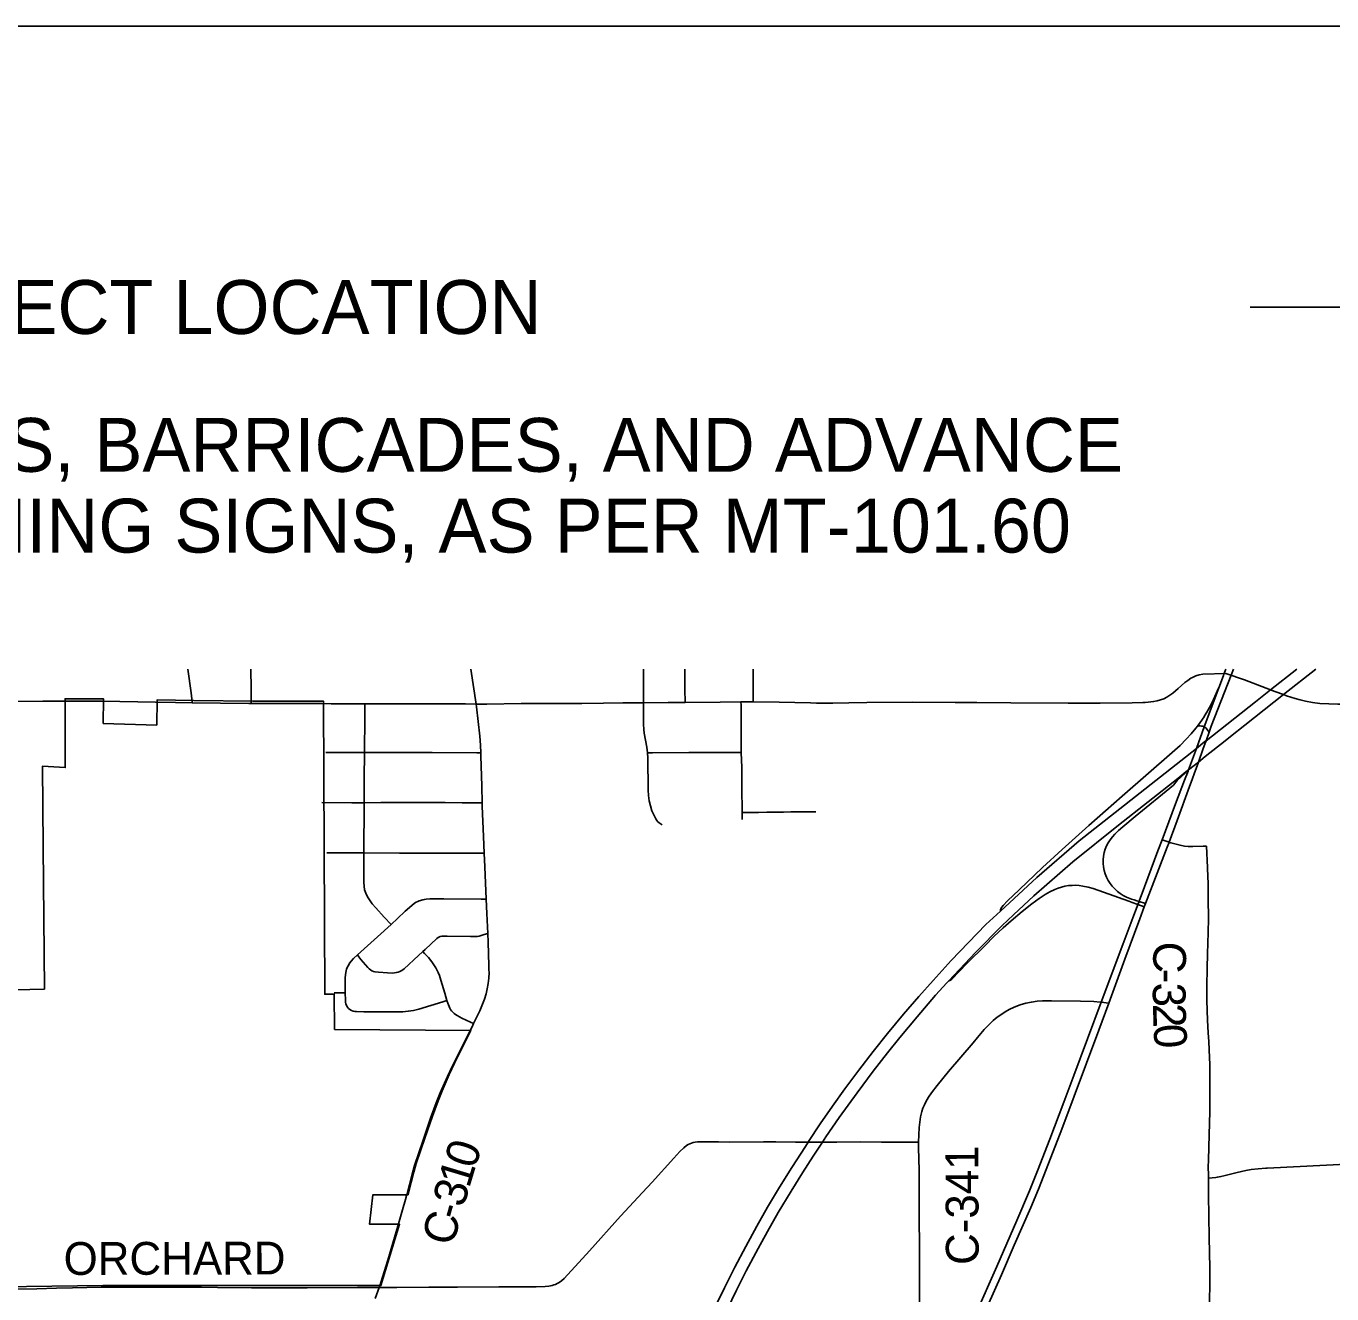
# Model space of a CAD drawing. Extents: x 40529 to 41139, y 15164 to 15584.
# Drawn here: x 40644 to 40711.9, y 15518.4 to 15584.3 of the extents above; entities that cross this region are included whole.
import ezdxf

# ---------------------------------------------------------------- set-up
doc = ezdxf.new("R2010")
doc.units = 0
for name, color, linetype in [('GM_X_Corporation', 7, 'Continuous'), ('GM_X_County_Road', 7, 'Continuous'), ('GM_X_County_Road_Text', 7, 'Continuous'), ('GM_X_Interchange_Ramps', 7, 'Continuous'), ('GM_X_Interstate_Route', 7, 'Continuous'), ('GM_X_State_Route', 7, 'Continuous'), ('GM_X_Township_Road', 7, 'Continuous'), ('SC_Scratch1', 7, 'Continuous'), ('SH_Data', 7, 'Continuous'), ('SH_Text', 7, 'Continuous')]:
    doc.layers.add(name, color=color, linetype=linetype)

msp = doc.modelspace()

# ---------------------------------------------------------------- linework, layer by layer
at = {"layer": 'GM_X_Corporation'}
msp.add_lwpolyline([(40633.428, 15533.98), (40645, 15534.243), (40644.942, 15541.646), (40644.909, 15545.837), (40646.082, 15545.763), (40646.076, 15549.343), (40648.075, 15549.336), (40648.062, 15548.055), (40650.838, 15547.972), (40650.859, 15549.285), (40652.768, 15549.256), (40655.835, 15549.22), (40659.511, 15549.213), (40659.574, 15533.977), (40660.069, 15533.984), (40660.082, 15532.153), (40667.169, 15532.086), (40666.326, 15530.389), (40666.05, 15529.799), (40665.675, 15528.948), (40665.465, 15528.43), (40665.172, 15527.644), (40664.775, 15526.501), (40664.33, 15525.179), (40664.204, 15524.732), (40663.932, 15523.646), (40663.906, 15523.553), (40662.067, 15523.549), (40661.908, 15522.019), (40663.467, 15522.024), (40662.492, 15518.827), (40648.03, 15518.837), (40632.149, 15518.628)], dxfattribs=at)
at = {"layer": 'GM_X_County_Road'}
for p, q in [((40667.442, 15549.06), (40667.161, 15550.883)), ((40647.999, 15549.211), (40650.78, 15549.16)), ((40659.423, 15549.088), (40659.915, 15549.082)), ((40675.065, 15549.123), (40676.138, 15549.135)), ((40703.102, 15542.012), (40703.464, 15541.887)), ((40705.414, 15541.679), (40705.47, 15540.568)), ((40705.48, 15540.149), (40705.492, 15539.688))]:
    msp.add_line(p, q, dxfattribs=at)
for points in [[(40702.228, 15549.146), (40702.385, 15549.156), (40702.659, 15549.19), (40702.84, 15549.228), (40703.016, 15549.279), (40703.187, 15549.345), (40703.35, 15549.428), (40703.505, 15549.525), (40703.653, 15549.634), (40703.936, 15549.874), (40704.29, 15550.181), (40704.439, 15550.297), (40704.595, 15550.404), (40704.676, 15550.452), (40704.849, 15550.531), (40705.031, 15550.585), (40705.219, 15550.613), (40706.419, 15550.658)], [(40706.419, 15550.658), (40707.391, 15550.324), (40708.745, 15549.806), (40708.957, 15549.724), (40709.415, 15549.557), (40709.572, 15549.5), (40710.017, 15549.355), (40710.288, 15549.281), (40710.562, 15549.218), (40710.93, 15549.15), (40711.301, 15549.103), (40711.767, 15549.07), (40712.233, 15549.056), (40712.768, 15549.055)], [(40629.727, 15549.202), (40632.453, 15549.203), (40633.472, 15549.215), (40634.586, 15549.231), (40635.982, 15549.24), (40637.122, 15549.236), (40638.834, 15549.216), (40640.349, 15549.212), (40642.683, 15549.194), (40644.917, 15549.219), (40646.002, 15549.217)], [(40646.002, 15549.217), (40647.802, 15549.214), (40647.999, 15549.211)], [(40650.78, 15549.16), (40651.808, 15549.141), (40652.687, 15549.13)], [(40652.687, 15549.13), (40655.628, 15549.095), (40655.75, 15549.095)], [(40655.75, 15549.095), (40657.396, 15549.09), (40658.508, 15549.099), (40659.423, 15549.088)], [(40659.915, 15549.082), (40659.991, 15549.081), (40661.654, 15549.081)], [(40661.654, 15549.081), (40666.89, 15549.07), (40667.442, 15549.06)], [(40667.442, 15549.06), (40668.008, 15549.057), (40669.778, 15549.087), (40672.947, 15549.102), (40674.065, 15549.112), (40675.065, 15549.123)], [(40667.687, 15546.537), (40667.67, 15546.931), (40667.632, 15547.395), (40667.458, 15548.915), (40667.442, 15549.06)], [(40676.138, 15549.135), (40677.422, 15549.149), (40678.304, 15549.154)], [(40678.304, 15549.154), (40680.125, 15549.165), (40681.212, 15549.173)], [(40681.212, 15549.173), (40681.617, 15549.176), (40681.84, 15549.175)], [(40681.84, 15549.175), (40683.199, 15549.169), (40684.819, 15549.126)], [(40684.819, 15549.126), (40685.142, 15549.117), (40685.978, 15549.107), (40686.816, 15549.122), (40687.749, 15549.14), (40690.122, 15549.157)], [(40690.122, 15549.157), (40692.349, 15549.149), (40693.469, 15549.142), (40695.24, 15549.129), (40698.222, 15549.118), (40699.887, 15549.109), (40701.553, 15549.124), (40702.108, 15549.139), (40702.228, 15549.146)], [(40667.753, 15543.936), (40667.733, 15544.788), (40667.694, 15546.371), (40667.687, 15546.537)], [(40667.866, 15541.321), (40667.825, 15542.182), (40667.757, 15543.765), (40667.753, 15543.936)], [(40703.464, 15541.887), (40703.566, 15541.852), (40704.042, 15541.724), (40704.276, 15541.678), (40704.459, 15541.659), (40704.698, 15541.659), (40705.237, 15541.673), (40705.414, 15541.679)], [(40667.97, 15538.924), (40667.9, 15540.599), (40667.866, 15541.321)], [(40705.47, 15540.568), (40705.472, 15540.489), (40705.48, 15540.149)], [(40705.492, 15539.688), (40705.501, 15538.944), (40705.508, 15537.922), (40705.49, 15537.19), (40705.471, 15536.071), (40705.454, 15535.327)], [(40668.044, 15537.134), (40668.001, 15538.177), (40667.97, 15538.924)], [(40668.112, 15535.245), (40668.111, 15535.475), (40668.063, 15536.687), (40668.044, 15537.134)], [(40667.31, 15532.457), (40667.631, 15533.122), (40667.779, 15533.464), (40667.876, 15533.726), (40667.959, 15533.993), (40668.025, 15534.265), (40668.073, 15534.541), (40668.101, 15534.821), (40668.113, 15535.101), (40668.112, 15535.245)], [(40705.454, 15535.327), (40705.432, 15534.394), (40705.432, 15533.649), (40705.463, 15532.624), (40705.498, 15531.976), (40705.534, 15531.514), (40705.573, 15530.676), (40705.579, 15530.349), (40705.587, 15529.93), (40705.581, 15527.879), (40705.555, 15526.667), (40705.516, 15525.362), (40705.503, 15524.989), (40705.513, 15524.586), (40705.522, 15524.408)], [(40693.277, 15531.449), (40693.511, 15531.725), (40693.861, 15532.14), (40694.123, 15532.421), (40694.325, 15532.608), (40694.537, 15532.786), (40694.769, 15532.944), (40695.001, 15533.102), (40695.228, 15533.225), (40695.499, 15533.343), (40695.731, 15533.427), (40696.017, 15533.506), (40696.313, 15533.57), (40696.604, 15533.615), (40696.886, 15533.639), (40697.349, 15533.644), (40698.869, 15533.615), (40699.554, 15533.595), (40699.885, 15533.571), (40699.937, 15533.564)], [(40699.937, 15533.564), (40699.958, 15533.561), (40700.314, 15533.521), (40700.334, 15533.519)], [(40667.073, 15531.978), (40667.267, 15532.368), (40667.31, 15532.457)], [(40663.806, 15523.425), (40663.814, 15523.454), (40663.84, 15523.547), (40664.111, 15524.632), (40664.238, 15525.078), (40664.682, 15526.399), (40665.078, 15527.541), (40665.371, 15528.326), (40665.581, 15528.844), (40665.955, 15529.694), (40666.231, 15530.283), (40667.073, 15531.978)], [(40690.447, 15526.289), (40690.45, 15526.672), (40690.472, 15527.045), (40690.503, 15527.324), (40690.546, 15527.611), (40690.615, 15527.882), (40690.67, 15528.055), (40690.749, 15528.233), (40690.818, 15528.385), (40690.956, 15528.622), (40691.123, 15528.859), (40691.415, 15529.229), (40692.006, 15529.954), (40693.277, 15531.449)], [(40662.402, 15518.733), (40663.317, 15518.731), (40664.993, 15518.747), (40665.737, 15518.752), (40666.482, 15518.756), (40668.616, 15518.769), (40670.106, 15518.768), (40670.57, 15518.765), (40671.035, 15518.781), (40671.217, 15518.799), (40671.396, 15518.836), (40671.484, 15518.862), (40671.569, 15518.894), (40671.652, 15518.931), (40671.732, 15518.974), (40671.808, 15519.024), (40671.88, 15519.078), (40672.013, 15519.203), (40673.331, 15520.645), (40674.949, 15522.44), (40676.085, 15523.67), (40676.591, 15524.216), (40677.717, 15525.455), (40678.038, 15525.795), (40678.244, 15525.987), (40678.371, 15526.106), (40678.465, 15526.165), (40678.549, 15526.205), (40678.642, 15526.244), (40678.731, 15526.274), (40678.825, 15526.289), (40678.943, 15526.303), (40679.113, 15526.307), (40680.047, 15526.3), (40680.606, 15526.292), (40682.374, 15526.302), (40683.027, 15526.298), (40684.052, 15526.291), (40684.706, 15526.292), (40685.445, 15526.292), (40685.895, 15526.293)], [(40685.895, 15526.293), (40686.195, 15526.293), (40687.406, 15526.299), (40688.524, 15526.295), (40689.8, 15526.289), (40690.384, 15526.289), (40690.447, 15526.289)], [(40690.486, 15517.482), (40690.499, 15519.736), (40690.48, 15523.462), (40690.467, 15524.818), (40690.446, 15526.018), (40690.447, 15526.289)], [(40705.522, 15524.408), (40705.892, 15524.453), (40705.98, 15524.468), (40706.069, 15524.483), (40706.158, 15524.502), (40706.316, 15524.542), (40707.001, 15524.71), (40707.458, 15524.813), (40707.735, 15524.86), (40708.106, 15524.907), (40708.504, 15524.939), (40708.571, 15524.944), (40711.644, 15525.091), (40712.669, 15525.151), (40712.857, 15525.156), (40713.047, 15525.147), (40713.141, 15525.136), (40713.326, 15525.095), (40713.416, 15525.064), (40713.494, 15525.031)], [(40663.375, 15521.926), (40663.589, 15522.649), (40663.806, 15523.425)], [(40662.402, 15518.733), (40662.448, 15518.862), (40662.493, 15518.989), (40662.847, 15520.147), (40663.375, 15521.926)], [(40632.089, 15518.534), (40635.071, 15518.557), (40636.375, 15518.588), (40637.214, 15518.598), (40638.425, 15518.618), (40640.566, 15518.622), (40641.495, 15518.628), (40644.605, 15518.668), (40645.628, 15518.692), (40646.463, 15518.707), (40647.954, 15518.743), (40650.095, 15518.748), (40653.17, 15518.74), (40654.005, 15518.73), (40655.772, 15518.72), (40658.661, 15518.713), (40661.268, 15518.735), (40662.402, 15518.733)]]:
    msp.add_lwpolyline(points, dxfattribs=at)
at = {"layer": 'GM_X_Interchange_Ramps'}
for points in [[(40706.059, 15549.913), (40706.039, 15549.9), (40705.767, 15549.31), (40705.565, 15548.892), (40705.431, 15548.647), (40705.314, 15548.455)], [(40704.938, 15547.921), (40704.851, 15547.806), (40704.613, 15547.521), (40704.363, 15547.246), (40704.035, 15546.917), (40703.625, 15546.539), (40701.034, 15544.281), (40699.286, 15542.751), (40697.903, 15541.509), (40696.882, 15540.56), (40695.665, 15539.412), (40695.07, 15538.833), (40694.847, 15538.594), (40694.774, 15538.501), (40694.726, 15538.42), (40694.707, 15538.373), (40694.698, 15538.336), (40694.695, 15538.302)], [(40705.314, 15548.455), (40705.286, 15548.409), (40705.076, 15548.102), (40704.938, 15547.921)], [(40705.296, 15547.88), (40705.26, 15547.897), (40705.215, 15547.91), (40705.151, 15547.921), (40705.08, 15547.928), (40705.029, 15547.928), (40704.997, 15547.926), (40704.97, 15547.924), (40704.938, 15547.921)], [(40705.548, 15547.601), (40705.533, 15547.623), (40705.483, 15547.699), (40705.396, 15547.804), (40705.332, 15547.859), (40705.296, 15547.88)], [(40702.245, 15538.701), (40701.908, 15538.805), (40701.797, 15538.839), (40701.644, 15538.887), (40701.52, 15538.927), (40701.428, 15538.959), (40701.254, 15539.027), (40701.088, 15539.112), (40700.93, 15539.212), (40700.782, 15539.326), (40700.644, 15539.452), (40700.516, 15539.589), (40700.402, 15539.737), (40700.301, 15539.894), (40700.215, 15540.06), (40700.145, 15540.233), (40700.096, 15540.413), (40700.063, 15540.596), (40700.045, 15540.782), (40700.047, 15540.969), (40700.065, 15541.155), (40700.097, 15541.34), (40700.149, 15541.518), (40700.217, 15541.692), (40700.304, 15541.856), (40700.404, 15542.013), (40700.519, 15542.16), (40700.642, 15542.299), (40700.844, 15542.495), (40701.054, 15542.681), (40701.703, 15543.217), (40703.69, 15544.856), (40703.886, 15545.087), (40704.298, 15545.475), (40704.316, 15545.494), (40704.335, 15545.536)], [(40692.009, 15534.681), (40692.044, 15534.687), (40692.075, 15534.696), (40692.105, 15534.714), (40692.165, 15534.766), (40692.973, 15535.59), (40693.901, 15536.513), (40694.362, 15536.976), (40694.837, 15537.425), (40695.255, 15537.797), (40695.826, 15538.277), (40696.337, 15538.685), (40696.711, 15538.964), (40697.022, 15539.17), (40697.266, 15539.308), (40697.519, 15539.427), (40697.693, 15539.494), (40697.871, 15539.55), (40698.053, 15539.593), (40698.236, 15539.624), (40698.422, 15539.639), (40698.608, 15539.641), (40698.794, 15539.628), (40698.979, 15539.604), (40699.253, 15539.548), (40699.523, 15539.473), (40700.053, 15539.294), (40701.368, 15538.813), (40701.543, 15538.748), (40701.844, 15538.643), (40702.178, 15538.526)]]:
    msp.add_lwpolyline(points, dxfattribs=at)
at = {"layer": 'GM_X_Interstate_Route'}
for points in [[(40684.723, 15526.317), (40685.333, 15527.234), (40685.967, 15528.154), (40686.617, 15529.063), (40687.34, 15530.035), (40688.079, 15530.994), (40688.835, 15531.941), (40689.666, 15532.945), (40690.454, 15533.865), (40691.197, 15534.701), (40692.14, 15535.732), (40693.94, 15537.598), (40694.695, 15538.302), (40696.589, 15540.047), (40698.796, 15541.955), (40704.884, 15546.758), (40705.331, 15547.111), (40705.388, 15547.156), (40707.964, 15549.188), (40708.745, 15549.806), (40710.109, 15550.883)], [(40706.667, 15547.381), (40707.41, 15547.972), (40709.415, 15549.557), (40711.091, 15550.883)], [(40705.342, 15546.332), (40706.388, 15547.159), (40706.667, 15547.381)], [(40703.913, 15545.202), (40704.335, 15545.536), (40704.475, 15545.646), (40704.99, 15546.053), (40705.342, 15546.332)], [(40695.38, 15538.103), (40696.43, 15539.089), (40698.455, 15540.871), (40700.834, 15542.768), (40703.913, 15545.202)], [(40685.445, 15526.292), (40685.631, 15526.571), (40686.316, 15527.571), (40687.243, 15528.857), (40688.082, 15529.977), (40688.826, 15530.935), (40689.468, 15531.735), (40690.365, 15532.809), (40691.324, 15533.924), (40691.907, 15534.574), (40692.009, 15534.681), (40693.398, 15536.148), (40694.789, 15537.548), (40695.38, 15538.103)], [(40664.908, 15483.496), (40667.468, 15489.094), (40668.323, 15490.959), (40670.372, 15495.457), (40671.634, 15498.213), (40671.653, 15498.253), (40671.967, 15498.932), (40673.396, 15502.073), (40674.83, 15505.21), (40677, 15509.96), (40678.476, 15513.18), (40679.946, 15516.404), (40680.496, 15517.588), (40680.984, 15518.596), (40681.489, 15519.595), (40682.099, 15520.751), (40682.591, 15521.651), (40683.149, 15522.622), (40683.815, 15523.746), (40684.402, 15524.699), (40684.957, 15525.562), (40685.445, 15526.292)], [(40679.823, 15517.622), (40680.352, 15518.712), (40680.897, 15519.794), (40681.461, 15520.866), (40682.043, 15521.928), (40682.597, 15522.9), (40683.217, 15523.941), (40683.854, 15524.972), (40684.558, 15526.07), (40684.706, 15526.292), (40684.723, 15526.317)]]:
    msp.add_lwpolyline(points, dxfattribs=at)
at = {"layer": 'GM_X_State_Route'}
for p, q in [((40706.82, 15550.883), (40706.701, 15550.561)), ((40705.242, 15546.752), (40705.323, 15546.975)), ((40704.837, 15545.63), (40704.918, 15545.856))]:
    msp.add_line(p, q, dxfattribs=at)
for points in [[(40705.296, 15547.88), (40706.059, 15549.913), (40706.296, 15550.545), (40706.321, 15550.612), (40706.423, 15550.883)], [(40705.323, 15546.975), (40705.333, 15547.003), (40705.388, 15547.156), (40705.548, 15547.601), (40705.662, 15547.914), (40706.7, 15550.562)], [(40701.844, 15538.643), (40701.908, 15538.805), (40701.929, 15538.865), (40702.007, 15539.089), (40702.887, 15541.443), (40703.102, 15542.012), (40703.807, 15543.883), (40704.275, 15545.105), (40704.45, 15545.578), (40704.475, 15545.646), (40704.884, 15546.758), (40705.296, 15547.88)], [(40704.918, 15545.856), (40704.99, 15546.053), (40705.242, 15546.752)], [(40702.178, 15538.526), (40702.245, 15538.701), (40703.366, 15541.619), (40703.446, 15541.84), (40703.464, 15541.887), (40703.881, 15543.018), (40704.527, 15544.778), (40704.612, 15545.009), (40704.837, 15545.63)], [(40693.42, 15517.354), (40694.508, 15519.826), (40695.553, 15522.217), (40696.21, 15523.76), (40696.631, 15524.796), (40697.272, 15526.446), (40697.988, 15528.366), (40698.513, 15529.759), (40699.937, 15533.564), (40701.058, 15536.561), (40701.586, 15537.954), (40701.808, 15538.548), (40701.844, 15538.643)], [(40701.168, 15535.797), (40701.94, 15537.906), (40702.178, 15538.526)], [(40691.434, 15511.871), (40692.936, 15515.309), (40694.748, 15519.398), (40695.416, 15520.936), (40696.278, 15522.898), (40696.671, 15523.843), (40697.323, 15525.488), (40697.886, 15526.968), (40699.808, 15532.115), (40700.334, 15533.519), (40701.168, 15535.797)]]:
    msp.add_lwpolyline(points, dxfattribs=at)
at = {"layer": 'GM_X_Township_Road'}
for p, q in [((40681.28, 15543.069), (40681.276, 15543.43)), ((40660.065, 15534.052), (40660.634, 15534.058))]:
    msp.add_line(p, q, dxfattribs=at)
for points in [[(40652.687, 15549.13), (40652.682, 15549.182), (40652.633, 15549.656), (40652.464, 15550.883)], [(40655.75, 15549.095), (40655.75, 15549.139), (40655.746, 15549.383), (40655.742, 15549.859), (40655.724, 15550.883)], [(40676.138, 15549.135), (40676.138, 15549.349), (40676.141, 15550.883)], [(40678.304, 15549.154), (40678.302, 15549.294), (40678.298, 15549.692), (40678.298, 15550.883)], [(40681.84, 15549.175), (40681.84, 15549.345), (40681.838, 15550.883)], [(40661.642, 15546.547), (40661.648, 15547.042), (40661.651, 15547.878), (40661.654, 15548.983), (40661.654, 15549.081)], [(40676.348, 15546.532), (40676.317, 15546.823), (40676.187, 15547.556), (40676.163, 15547.74), (40676.142, 15548.018), (40676.136, 15548.296), (40676.142, 15548.761), (40676.138, 15549.135)], [(40681.226, 15546.548), (40681.216, 15546.88), (40681.213, 15549.01), (40681.212, 15549.173)], [(40659.639, 15546.55), (40659.889, 15546.546), (40661.642, 15546.547)], [(40661.623, 15543.938), (40661.623, 15545.183), (40661.642, 15546.547)], [(40661.642, 15546.547), (40662.466, 15546.548), (40665.153, 15546.54), (40667.484, 15546.537), (40667.687, 15546.537)], [(40676.348, 15546.532), (40676.419, 15546.53), (40676.607, 15546.525), (40678.495, 15546.541), (40680.335, 15546.549), (40681.071, 15546.548), (40681.226, 15546.548)], [(40681.276, 15543.43), (40681.262, 15544.743), (40681.256, 15545.394), (40681.25, 15545.765), (40681.226, 15546.548)], [(40677.114, 15542.792), (40676.953, 15542.884), (40676.885, 15542.947), (40676.829, 15543.019), (40676.781, 15543.099), (40676.696, 15543.264), (40676.586, 15543.521), (40676.503, 15543.777), (40676.442, 15544.041), (40676.401, 15544.317), (40676.383, 15544.596), (40676.363, 15546.268), (40676.348, 15546.532)], [(40659.424, 15543.946), (40660.983, 15543.931), (40661.623, 15543.938)], [(40661.605, 15541.324), (40661.623, 15543.882), (40661.623, 15543.938)], [(40661.623, 15543.938), (40662.493, 15543.941), (40663.667, 15543.941), (40664.797, 15543.941), (40665.838, 15543.941), (40666.716, 15543.936), (40667.244, 15543.936), (40667.658, 15543.936), (40667.753, 15543.936)], [(40681.276, 15543.43), (40681.46, 15543.431), (40681.552, 15543.432), (40681.598, 15543.432), (40681.649, 15543.432), (40681.7, 15543.432), (40681.75, 15543.433), (40681.852, 15543.433), (40682.115, 15543.435), (40682.56, 15543.44), (40682.866, 15543.444), (40683.429, 15543.45), (40683.803, 15543.454), (40684.128, 15543.458), (40684.441, 15543.461), (40684.534, 15543.461), (40685.099, 15543.464)], [(40659.683, 15541.338), (40660.373, 15541.337), (40661.605, 15541.324)], [(40663.021, 15537.612), (40662.668, 15537.988), (40662.226, 15538.468), (40662.046, 15538.683), (40661.934, 15538.831), (40661.831, 15538.986), (40661.742, 15539.151), (40661.705, 15539.236), (40661.673, 15539.324), (40661.648, 15539.414), (40661.618, 15539.598), (40661.602, 15539.784), (40661.599, 15540.25), (40661.605, 15541.324)], [(40661.605, 15541.324), (40663.458, 15541.313), (40665.978, 15541.313), (40667.66, 15541.32), (40667.866, 15541.321)], [(40663.021, 15537.612), (40663.352, 15537.913), (40663.752, 15538.296), (40664.098, 15538.599), (40664.244, 15538.711), (40664.322, 15538.76), (40664.405, 15538.801), (40664.49, 15538.834), (40664.668, 15538.887), (40664.757, 15538.907), (40664.848, 15538.921), (40665.031, 15538.934), (40665.767, 15538.939), (40667.711, 15538.928), (40667.804, 15538.926), (40667.97, 15538.924)], [(40661.27, 15536.019), (40661.619, 15536.342), (40662.312, 15536.963), (40663.021, 15537.612)], [(40664.676, 15536.2), (40664.79, 15536.303), (40665.397, 15536.879), (40665.477, 15536.936), (40665.567, 15536.973), (40665.663, 15536.991), (40665.945, 15536.994), (40667.149, 15536.98), (40667.425, 15536.976), (40667.515, 15536.983), (40667.603, 15536.998), (40667.868, 15537.08), (40668.044, 15537.134)], [(40660.634, 15534.058), (40660.641, 15534.821), (40660.655, 15535.009), (40660.689, 15535.194), (40660.713, 15535.285), (40660.744, 15535.374), (40660.784, 15535.459), (40660.883, 15535.619), (40660.939, 15535.694), (40661.067, 15535.831), (40661.27, 15536.019)], [(40661.27, 15536.019), (40661.346, 15535.922), (40661.452, 15535.785), (40661.816, 15535.372), (40661.88, 15535.307), (40661.948, 15535.247), (40662.021, 15535.198), (40662.101, 15535.164), (40662.188, 15535.143), (40662.37, 15535.12), (40662.833, 15535.093), (40663.111, 15535.082), (40663.203, 15535.089), (40663.294, 15535.104), (40663.384, 15535.126), (40663.471, 15535.157), (40663.552, 15535.199), (40663.629, 15535.246), (40663.703, 15535.298), (40664.453, 15535.985), (40664.653, 15536.18), (40664.676, 15536.2)], [(40665.929, 15533.646), (40665.81, 15534.04), (40665.613, 15534.709), (40665.532, 15534.955), (40665.47, 15535.105), (40665.346, 15535.347), (40665.249, 15535.509), (40665.139, 15535.665), (40664.959, 15535.882), (40664.764, 15536.101), (40664.676, 15536.2)], [(40665.929, 15533.646), (40665.714, 15533.581), (40664.466, 15533.207), (40664.194, 15533.139), (40663.919, 15533.093), (40663.641, 15533.066), (40663.269, 15533.06), (40662.431, 15533.065), (40661.605, 15533.066), (40661.232, 15533.077), (40661.139, 15533.085), (40661.048, 15533.102), (40660.96, 15533.132), (40660.878, 15533.177), (40660.809, 15533.238), (40660.753, 15533.312), (40660.709, 15533.394), (40660.677, 15533.482), (40660.656, 15533.573), (40660.645, 15533.665), (40660.634, 15534.058)], [(40667.31, 15532.457), (40667.15, 15532.531), (40666.7, 15532.737), (40666.452, 15532.869), (40666.374, 15532.919), (40666.3, 15532.976), (40666.231, 15533.04), (40666.168, 15533.11), (40666.112, 15533.186), (40666.068, 15533.261), (40665.97, 15533.51), (40665.929, 15533.646)], [(40705.536, 15515.891), (40705.552, 15516.594), (40705.588, 15519.097), (40705.581, 15519.749), (40705.551, 15521.328), (40705.514, 15523.547), (40705.522, 15524.408)], [(40662.189, 15518.159), (40662.402, 15518.733)]]:
    msp.add_lwpolyline(points, dxfattribs=at)
at = {"layer": 'SC_Scratch1'}
msp.add_lwpolyline([(40528.651, 15584.313), (41138.651, 15584.313), (41138.651, 15164.313), (40528.651, 15164.313)], close=True, dxfattribs=at)
at = {"layer": 'SH_Data'}
msp.add_line((40707.682, 15569.708), (40724.091, 15569.708), dxfattribs=at)

# ---------------------------------------------------------------- texts
at = {"layer": 'GM_X_County_Road_Text'}
for s, height, rotation, p in [('C', 1.706, 268.61822, (40702.663, 15536.735)), ('-', 1.706, 269.10866, (40702.629, 15535.318)), ('3', 1.706, 270.22533, (40702.618, 15534.581)), ('2', 1.706, 271.58131, (40702.623, 15533.486)), ('0', 1.706, 272.92246, (40702.653, 15532.392)), ('0', 1.706, 72.08839, (40667.379, 15524.849)), ('C-341', 1.7063, 90.27519, (40693.574, 15519.907)), ('1', 1.706, 73.29975, (40667.079, 15523.851)), ('3', 1.706, 74.00956, (40666.791, 15522.846)), ('-', 1.706, 74.43201, (40666.604, 15522.175)), ('C', 1.706, 74.58912, (40666.232, 15520.825)), ('ORCHARD', 1.7063, 0.14069, (40646.001, 15519.383))]:
    msp.add_text(s, height=height, rotation=rotation, dxfattribs=at).set_placement(p)
at = {"layer": 'SH_Text'}
for s, p in [('  - PROJECT LOCATION', (40628.825, 15568.308)), ('  - GATES, BARRICADES, AND ADVANCE ', (40628.458, 15561.141)), ('    WARNING SIGNS, AS PER MT-101.60', (40628.458, 15556.941))]:
    msp.add_text(s, height=2.8, dxfattribs=at).set_placement(p)

doc.saveas('drawing.dxf')
